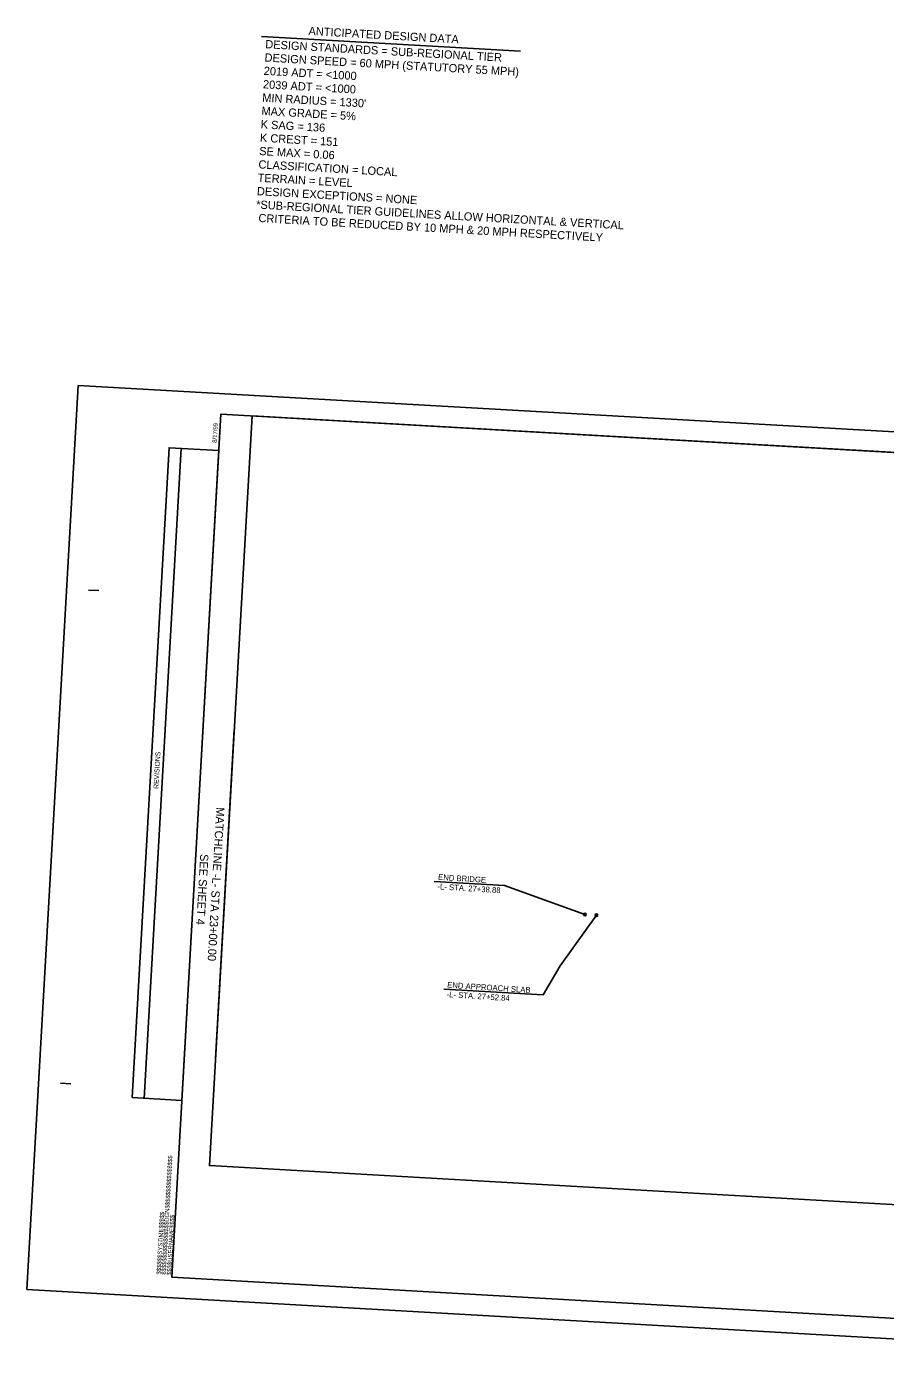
# Model space of a CAD drawing. Extents: x 2604316 to 2606605, y 617090 to 619543.
# Drawn here: x 2604316 to 2605358, y 617913 to 619543 of the extents above; entities that cross this region are included whole.
import ezdxf

# ---------------------------------------------------------------- set-up
doc = ezdxf.new("R2010")
doc.units = 0
for name, color, linetype in [('Prop Horizontal Alignment', 7, 'Continuous'), ('Prop Horizontal Alignment Station Label', 7, 'Continuous'), ('Scratch_Level_1', 7, 'Continuous'), ('Sheet Block Revision CELL', 7, 'Continuous'), ('Sheet Block System Information CELL', 7, 'Continuous'), ('Sheet Data Text CELL', 7, 'Continuous'), ('Sheet Plan And Profile CELL', 7, 'Continuous'), ('Stewart Plot Border Xerox6279 and LJ5000', 7, 'Continuous')]:
    doc.layers.add(name, color=color, linetype=linetype)

msp = doc.modelspace()

# ---------------------------------------------------------------- linework, layer by layer
at = {"layer": 'Prop Horizontal Alignment'}
for q in [(2604567.6, 618689.3), (2604544.9, 618289.9)]:
    msp.add_line((2604556.2, 618489.6), q, dxfattribs=at)
at = {"layer": 'Prop Horizontal Alignment Station Label'}
for p, q in [((2604895.7, 618500), (2604810.6, 618504.8)), ((2604895.7, 618500), (2604993.6, 618464.7)), ((2604942.7, 618367), (2604822.4, 618373.9))]:
    msp.add_line(p, q, dxfattribs=at)
msp.add_lwpolyline([(2604942.7, 618367), (2604963.6, 618402.2), (2605007.6, 618463.9)], dxfattribs=at)
for centre in [(2604993.6, 618464.7), (2605007.6, 618463.9)]:
    msp.add_circle(centre, 1.5, dxfattribs=at)
at = {"layer": 'Scratch_Level_1'}
msp.add_lwpolyline([(2606037.7, 618786.5), (2605837.9, 618797.8), (2605849.4, 618998.6), (2604589.3, 619070.3), (2604537.4, 618159.7), (2605997.2, 618076.6)], close=True, dxfattribs=at)
msp.add_lwpolyline([(2606037.7, 618786.5), (2605837.9, 618797.8), (2605849.4, 618998.6), (2604589.3, 619070.3), (2604537.4, 618159.7), (2605997.2, 618076.6)], close=True, dxfattribs=at)
at = {"layer": 'Sheet Block Revision CELL'}
msp.add_line((2604458.1, 618241.4), (2604503.1, 619030.8), dxfattribs=at)
msp.add_lwpolyline([(2604443.6, 618242.3), (2604488.5, 619031.6), (2604549, 619028.2), (2604504, 618238.8)], close=True, dxfattribs=at)
at = {"layer": 'Sheet Block System Information CELL'}
msp.add_line((2604491.8, 618024.2), (2604491.8, 618024.2), dxfattribs=at)
at = {"layer": 'Sheet Data Text CELL'}
msp.add_line((2604600.7, 619531.3), (2604915.2, 619513.4), dxfattribs=at)
at = {"layer": 'Sheet Plan And Profile CELL'}
for p, q in [((2604390.6, 618858.8), (2604403.1, 618858.1)), ((2604356.5, 618259.8), (2604369, 618259)), ((2604491.8, 618024.2), (2604491.8, 618024.2)), ((2604491.8, 618024.2), (2604491.8, 618024.2)), ((2604491.8, 618024.2), (2604491.8, 618024.2)), ((2604491.8, 618024.2), (2604491.8, 618024.2)), ((2604491.8, 618024.2), (2604491.8, 618024.2))]:
    msp.add_line(p, q, dxfattribs=at)
msp.add_lwpolyline([(2606049.1, 618987.2), (2604551.5, 619072.5), (2604491.8, 618024.2), (2605989.4, 617938.9)], close=True, dxfattribs=at)
at = {"layer": 'Stewart Plot Border Xerox6279 and LJ5000'}
msp.add_lwpolyline([(2604315.7, 618009.2), (2606012.9, 617912.5), (2606075.5, 619010.7), (2604378.2, 619107.4)], close=True, dxfattribs=at)

# ---------------------------------------------------------------- texts
at = {"layer": 'Prop Horizontal Alignment'}
for s, p in [('MATCHLINE -L- STA 23+00.00', (2604545.9, 618595.1)), ('SEE SHEET 4', (2604526.4, 618538.4))]:
    msp.add_text(s, height=10, rotation=266.7403, dxfattribs=at).set_placement(p)
at = {"layer": 'Prop Horizontal Alignment Station Label'}
for s, p in [('END BRIDGE', (2604815.1, 618506.8)), ('-L- STA. 27+38.88', (2604814.3, 618495.4)), ('END APPROACH SLAB', (2604826.1, 618375.8)), ('-L- STA. 27+52.84', (2604825.4, 618364.4))]:
    msp.add_text(s, height=7, rotation=356.3891, dxfattribs=at).set_placement(p)
at = {"layer": 'Sheet Block Revision CELL'}
msp.add_text('REVISIONS', height=6, rotation=86.7403, dxfattribs=at).set_placement((2604475.5, 618617.2))
at = {"layer": 'Sheet Block System Information CELL'}
for s, p in [('$$$$$$$$$$$$$$$$DGN$$$$$$$$$$$$$$$$', (2604484.3, 618027)), ('$$$$$$SYSTIME$$$$$', (2604478.3, 618027.3)), ('$$$$USERNAME$$$$', (2604490.9, 618026.6))]:
    msp.add_text(s, height=5.25, rotation=86.7403, dxfattribs=at).set_placement(p)
at = {"layer": 'Sheet Data Text CELL'}
for s, p in [('ANTICIPATED DESIGN DATA', (2604657.6, 619533.1)), ('DESIGN STANDARDS = SUB-REGIONAL TIER', (2604605.1, 619517)), ('DESIGN SPEED = 60 MPH (STATUTORY 55 MPH)', (2604604.2, 619500.8)), ('2019 ADT = <1000', (2604603.2, 619484.6)), ('2039 ADT = <1000', (2604602.3, 619468.3)), ("MIN RADIUS = 1330'", (2604601.4, 619452.1)), ('MAX GRADE = 5%', (2604600.5, 619435.9)), ('K SAG = 136', (2604599.5, 619419.7)), ('K CREST = 151', (2604598.6, 619403.4)), ('SE MAX = 0.06', (2604597.7, 619387.2)), ('CLASSIFICATION = LOCAL', (2604596.8, 619371)), ('TERRAIN = LEVEL', (2604595.8, 619354.8)), ('DESIGN EXCEPTIONS = NONE', (2604594.9, 619338.5)), ('*SUB-REGIONAL TIER GUIDELINES ALLOW HORIZONTAL & VERTICAL', (2604594, 619322.3)), (' CRITERIA TO BE REDUCED BY 10 MPH & 20 MPH RESPECTIVELY', (2604593.1, 619306.1))]:
    msp.add_text(s, height=10, rotation=356.7403, dxfattribs=at).set_placement(p)
at = {"layer": 'Sheet Plan And Profile CELL'}
msp.add_text('8/17/99', height=5.25, rotation=86.7403, dxfattribs=at).set_placement((2604546.3, 619037.5))

doc.saveas('drawing.dxf')
